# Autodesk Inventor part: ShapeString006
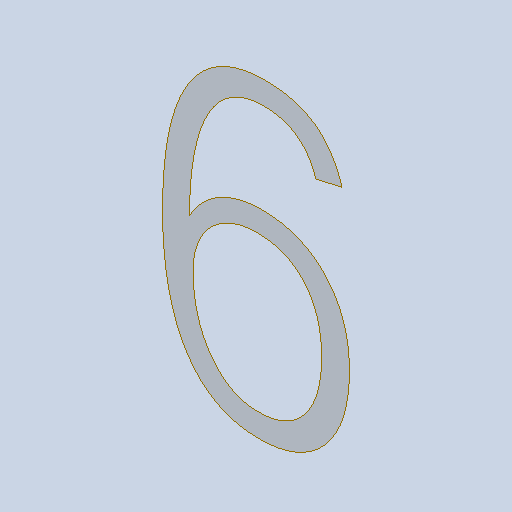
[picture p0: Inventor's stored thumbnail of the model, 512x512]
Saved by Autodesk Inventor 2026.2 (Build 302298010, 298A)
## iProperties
Created: 2026-10
Part Number: ShapeString006
Material: Générique
Document SubType Name: Modeling
Designer: mel
Density: 1 g/cm^3
Appearance: Par défaut
Author: mel
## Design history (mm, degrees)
feature "Composite1"
body "Srf1"
